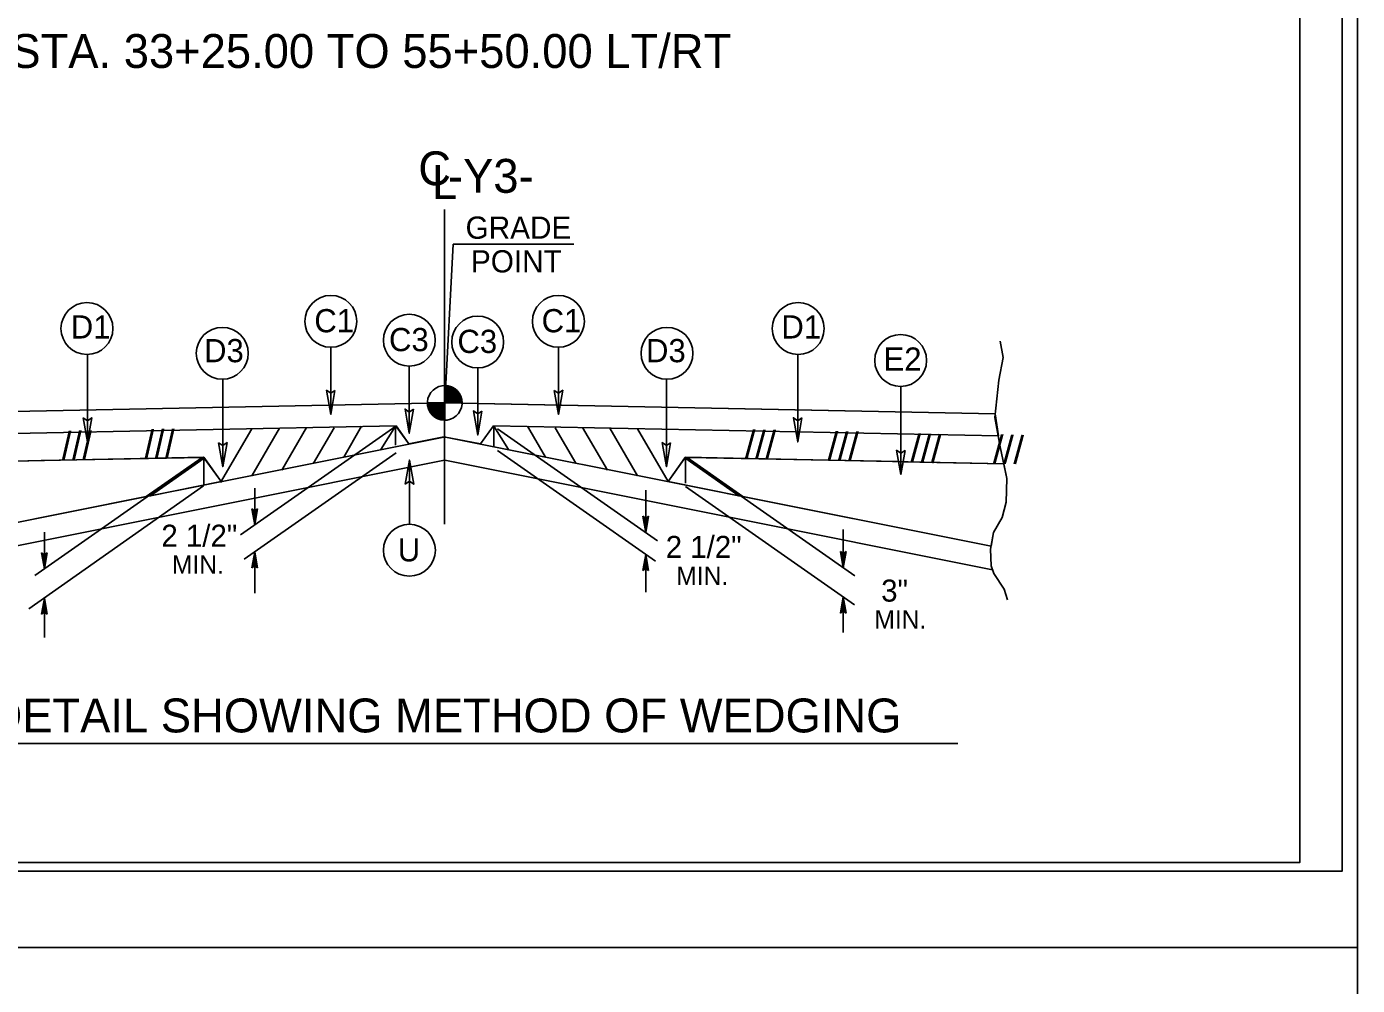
# Model space of a CAD drawing. Extents: x 1901718 to 1902220, y 193828 to 194187.
# Drawn here: x 1902095 to 1902134.24, y 194046.89 to 194075.18 of the extents above; entities that cross this region are included whole.
import ezdxf

# ---------------------------------------------------------------- set-up
doc = ezdxf.new("R2010")
doc.units = 0
for name, color, linetype in [('Old_Level_1', 7, 'Continuous'), ('Old_Level_11', 7, 'Continuous'), ('Old_Level_2', 7, 'Continuous'), ('Old_Level_20', 7, 'Continuous'), ('Old_Level_21', 7, 'Continuous'), ('Old_Level_3', 7, 'Continuous'), ('Prop Lane Arrow CELL', 7, 'Continuous'), ('Sheet Border Standard 30in CELL', 7, 'Continuous'), ('Sheet Cutting Line CELL', 7, 'Continuous'), ('Sheet Plot Border Inside CELL', 7, 'Continuous'), ('Sheet Plot Border Outside CELL', 7, 'Continuous')]:
    doc.layers.add(name, color=color, linetype=linetype)

msp = doc.modelspace()

# ---------------------------------------------------------------- linework, layer by layer
at = {"layer": 'Old_Level_1'}
for p, q in [((1902107.33, 194064.077), (1902107.33, 194064.588)), ((1902106.819, 194064.077), (1902107.33, 194064.077)), ((1902107.327, 194063.566), (1902107.327, 194064.071)), ((1902107.33, 194064.077), (1902107.33, 194063.566)), ((1902107.842, 194064.077), (1902107.33, 194064.077)), ((1902107.33, 194063.566), (1902107.33, 194064.077)), ((1902101.644, 194063.313), (1902100.721, 194061.732)), ((1902105.884, 194063.386), (1902101.309, 194060.183)), ((1902102.454, 194063.33), (1902101.638, 194061.928)), ((1902103.256, 194063.346), (1902102.523, 194062.089)), ((1902104.065, 194063.344), (1902103.457, 194062.303)), ((1902104.879, 194063.386), (1902104.35, 194062.478)), ((1902108.887, 194063.312), (1902113.6, 194060.011)), ((1902109.774, 194063.386), (1902110.304, 194062.478)), ((1902110.589, 194063.344), (1902111.197, 194062.303)), ((1902111.397, 194063.346), (1902112.131, 194062.089)), ((1902112.199, 194063.33), (1902113.016, 194061.928)), ((1902113.01, 194063.313), (1902113.919, 194061.755)), ((1902108.881, 194062.67), (1902113.548, 194059.403)), ((1902100.224, 194062.471), (1902090.84, 194062.283)), ((1902107.321, 194062.385), (1902091.207, 194059.162)), ((1902100.224, 194062.471), (1902095.242, 194058.982)), ((1902100.734, 194061.754), (1902100.224, 194062.471)), ((1902100.224, 194062.471), (1902100.224, 194061.652)), ((1902105.895, 194062.604), (1902101.418, 194059.469)), ((1902107.333, 194062.385), (1902123.484, 194059.154)), ((1902113.92, 194061.755), (1902114.429, 194062.471)), ((1902114.429, 194062.471), (1902123.814, 194062.283)), ((1902114.429, 194062.471), (1902114.429, 194061.71)), ((1902114.43, 194062.471), (1902119.42, 194058.976)), ((1902100.22, 194061.627), (1902095.069, 194058.001)), ((1902100.224, 194061.653), (1902098.59, 194061.326)), ((1902101.726, 194061.563), (1902101.726, 194060.475)), ((1902113.256, 194061.501), (1902113.256, 194060.253)), ((1902113.919, 194061.755), (1902116.064, 194061.326)), ((1902114.429, 194061.611), (1902119.411, 194058.121)), ((1902098.59, 194061.326), (1902091.213, 194059.851)), ((1902101.726, 194060.475), (1902101.642, 194060.952)), ((1902101.726, 194060.89), (1902101.642, 194060.952)), ((1902101.726, 194060.475), (1902101.654, 194060.943)), ((1902101.666, 194060.934), (1902101.726, 194060.475)), ((1902101.726, 194060.475), (1902101.678, 194060.926)), ((1902101.69, 194060.917), (1902101.726, 194060.475)), ((1902101.726, 194060.475), (1902101.702, 194060.908)), ((1902101.714, 194060.899), (1902101.726, 194060.475)), ((1902101.726, 194060.475), (1902101.811, 194060.952)), ((1902101.811, 194060.952), (1902101.726, 194060.89)), ((1902101.799, 194060.943), (1902101.726, 194060.475)), ((1902101.726, 194060.475), (1902101.786, 194060.934)), ((1902101.774, 194060.926), (1902101.726, 194060.475)), ((1902101.726, 194060.475), (1902101.762, 194060.917)), ((1902101.75, 194060.908), (1902101.726, 194060.475)), ((1902101.726, 194060.475), (1902101.738, 194060.899)), ((1902101.726, 194060.89), (1902101.726, 194060.475)), ((1902113.256, 194060.253), (1902113.172, 194060.731)), ((1902113.256, 194060.668), (1902113.172, 194060.731)), ((1902113.256, 194060.253), (1902113.183, 194060.722)), ((1902113.195, 194060.713), (1902113.256, 194060.253)), ((1902113.256, 194060.253), (1902113.208, 194060.704)), ((1902113.22, 194060.695), (1902113.256, 194060.253)), ((1902113.256, 194060.253), (1902113.231, 194060.686)), ((1902113.243, 194060.678), (1902113.256, 194060.253)), ((1902113.256, 194060.253), (1902113.34, 194060.731)), ((1902113.34, 194060.731), (1902113.256, 194060.668)), ((1902113.328, 194060.722), (1902113.256, 194060.253)), ((1902113.256, 194060.253), (1902113.316, 194060.713)), ((1902113.304, 194060.704), (1902113.256, 194060.253)), ((1902113.256, 194060.253), (1902113.292, 194060.695)), ((1902113.28, 194060.686), (1902113.256, 194060.253)), ((1902113.256, 194060.253), (1902113.268, 194060.678)), ((1902113.256, 194060.668), (1902113.256, 194060.253)), ((1902119.082, 194060.342), (1902119.082, 194059.213)), ((1902095.522, 194060.262), (1902095.522, 194059.177)), ((1902095.522, 194059.177), (1902095.437, 194059.655)), ((1902095.522, 194059.593), (1902095.437, 194059.655)), ((1902095.522, 194059.177), (1902095.449, 194059.647)), ((1902095.462, 194059.637), (1902095.522, 194059.177)), ((1902095.522, 194059.177), (1902095.475, 194059.629)), ((1902095.486, 194059.62), (1902095.522, 194059.177)), ((1902095.522, 194059.177), (1902095.498, 194059.611)), ((1902095.51, 194059.602), (1902095.522, 194059.177)), ((1902095.522, 194059.177), (1902095.606, 194059.655)), ((1902095.606, 194059.655), (1902095.522, 194059.593)), ((1902095.594, 194059.647), (1902095.522, 194059.177)), ((1902095.522, 194059.177), (1902095.582, 194059.637)), ((1902095.57, 194059.629), (1902095.522, 194059.177)), ((1902095.522, 194059.177), (1902095.558, 194059.62)), ((1902095.547, 194059.611), (1902095.522, 194059.177)), ((1902095.522, 194059.177), (1902095.534, 194059.602)), ((1902095.522, 194059.593), (1902095.522, 194059.177)), ((1902101.726, 194059.685), (1902101.642, 194059.207)), ((1902101.654, 194059.217), (1902101.726, 194059.685)), ((1902101.726, 194059.685), (1902101.666, 194059.225)), ((1902101.678, 194059.235), (1902101.726, 194059.685)), ((1902101.726, 194059.685), (1902101.69, 194059.243)), ((1902101.702, 194059.252), (1902101.726, 194059.685)), ((1902101.726, 194059.685), (1902101.714, 194059.261)), ((1902101.726, 194059.685), (1902101.726, 194058.459)), ((1902101.726, 194059.685), (1902101.811, 194059.207)), ((1902101.726, 194059.269), (1902101.726, 194059.685)), ((1902101.738, 194059.261), (1902101.726, 194059.685)), ((1902101.726, 194059.685), (1902101.75, 194059.252)), ((1902101.762, 194059.243), (1902101.726, 194059.685)), ((1902101.726, 194059.685), (1902101.774, 194059.235)), ((1902101.786, 194059.225), (1902101.726, 194059.685)), ((1902101.726, 194059.685), (1902101.799, 194059.217)), ((1902113.256, 194059.607), (1902113.172, 194059.13)), ((1902113.183, 194059.139), (1902113.256, 194059.607)), ((1902113.256, 194059.607), (1902113.195, 194059.148)), ((1902113.208, 194059.157), (1902113.256, 194059.607)), ((1902113.256, 194059.607), (1902113.22, 194059.166)), ((1902113.231, 194059.174), (1902113.256, 194059.607)), ((1902113.256, 194059.607), (1902113.243, 194059.183)), ((1902113.256, 194059.607), (1902113.256, 194058.491)), ((1902113.256, 194059.607), (1902113.34, 194059.13)), ((1902113.256, 194059.192), (1902113.256, 194059.607)), ((1902113.268, 194059.183), (1902113.256, 194059.607)), ((1902113.256, 194059.607), (1902113.28, 194059.174)), ((1902113.292, 194059.166), (1902113.256, 194059.607)), ((1902113.256, 194059.607), (1902113.304, 194059.157)), ((1902113.316, 194059.148), (1902113.256, 194059.607)), ((1902113.256, 194059.607), (1902113.328, 194059.139)), ((1902119.082, 194059.213), (1902118.998, 194059.69)), ((1902119.082, 194059.629), (1902118.998, 194059.69)), ((1902119.082, 194059.213), (1902119.01, 194059.681)), ((1902119.022, 194059.673), (1902119.082, 194059.213)), ((1902119.082, 194059.213), (1902119.033, 194059.665)), ((1902119.045, 194059.655), (1902119.082, 194059.213)), ((1902119.082, 194059.213), (1902119.058, 194059.647)), ((1902119.069, 194059.637), (1902119.082, 194059.213)), ((1902119.082, 194059.213), (1902119.166, 194059.69)), ((1902119.166, 194059.69), (1902119.082, 194059.629)), ((1902119.154, 194059.681), (1902119.082, 194059.213)), ((1902119.082, 194059.213), (1902119.142, 194059.673)), ((1902119.13, 194059.665), (1902119.082, 194059.213)), ((1902119.082, 194059.213), (1902119.117, 194059.655)), ((1902119.106, 194059.647), (1902119.082, 194059.213)), ((1902119.082, 194059.213), (1902119.094, 194059.637)), ((1902119.082, 194059.629), (1902119.082, 194059.213)), ((1902101.642, 194059.207), (1902101.726, 194059.269)), ((1902101.726, 194059.269), (1902101.811, 194059.207)), ((1902113.172, 194059.13), (1902113.256, 194059.192)), ((1902113.256, 194059.192), (1902113.34, 194059.13)), ((1902095.522, 194058.319), (1902095.437, 194057.842)), ((1902095.45, 194057.851), (1902095.522, 194058.319)), ((1902095.522, 194058.319), (1902095.462, 194057.86)), ((1902095.475, 194057.868), (1902095.522, 194058.319)), ((1902095.522, 194058.319), (1902095.486, 194057.877)), ((1902095.498, 194057.886), (1902095.522, 194058.319)), ((1902095.522, 194058.319), (1902095.51, 194057.894)), ((1902095.522, 194058.319), (1902095.522, 194057.159)), ((1902095.522, 194058.319), (1902095.606, 194057.842)), ((1902095.522, 194057.904), (1902095.522, 194058.319)), ((1902095.534, 194057.894), (1902095.522, 194058.319)), ((1902095.522, 194058.319), (1902095.547, 194057.886)), ((1902095.559, 194057.877), (1902095.522, 194058.319)), ((1902095.522, 194058.319), (1902095.57, 194057.868)), ((1902095.582, 194057.86), (1902095.522, 194058.319)), ((1902095.522, 194058.319), (1902095.594, 194057.851)), ((1902119.082, 194058.352), (1902118.998, 194057.875)), ((1902119.01, 194057.884), (1902119.082, 194058.352)), ((1902119.082, 194058.352), (1902119.022, 194057.893)), ((1902119.033, 194057.902), (1902119.082, 194058.352)), ((1902119.082, 194058.352), (1902119.045, 194057.911)), ((1902119.058, 194057.92), (1902119.082, 194058.352)), ((1902119.082, 194058.352), (1902119.069, 194057.928)), ((1902119.082, 194058.352), (1902119.082, 194057.305)), ((1902119.082, 194058.352), (1902119.166, 194057.875)), ((1902119.082, 194057.938), (1902119.082, 194058.352)), ((1902119.094, 194057.928), (1902119.082, 194058.352)), ((1902119.082, 194058.352), (1902119.106, 194057.92)), ((1902119.117, 194057.911), (1902119.082, 194058.352)), ((1902119.082, 194058.352), (1902119.13, 194057.902)), ((1902119.142, 194057.893), (1902119.082, 194058.352)), ((1902119.082, 194058.352), (1902119.154, 194057.884)), ((1902118.998, 194057.875), (1902119.082, 194057.938)), ((1902119.082, 194057.938), (1902119.166, 194057.875)), ((1902095.437, 194057.842), (1902095.522, 194057.904)), ((1902095.522, 194057.904), (1902095.606, 194057.842))]:
    msp.add_line(p, q, dxfattribs=at)
for points in [[(1902123.714, 194065.896), (1902123.8, 194065.42), (1902123.671, 194064.744), (1902123.555, 194063.649), (1902123.714, 194062.785), (1902123.901, 194061.849), (1902123.887, 194061.143), (1902123.771, 194060.697), (1902123.512, 194060.25), (1902123.426, 194059.761), (1902123.44, 194059.271), (1902123.526, 194059.04), (1902123.828, 194058.579), (1902123.929, 194058.262)], [(1902107.335, 194064.588), (1902107.335, 194064.588), (1902107.335, 194064.077)], [(1902107.345, 194064.588), (1902107.345, 194064.077)], [(1902107.356, 194064.588), (1902107.356, 194064.077)], [(1902107.366, 194064.587), (1902107.366, 194064.077)], [(1902107.377, 194064.587), (1902107.377, 194064.077)], [(1902107.386, 194064.585), (1902107.386, 194064.077)], [(1902107.397, 194064.585), (1902107.397, 194064.077)], [(1902107.406, 194064.583), (1902107.406, 194064.077)], [(1902107.417, 194064.581), (1902107.417, 194064.077)], [(1902107.427, 194064.579), (1902107.427, 194064.077)], [(1902107.438, 194064.578), (1902107.438, 194064.077)], [(1902107.448, 194064.575), (1902107.448, 194064.077)], [(1902107.458, 194064.572), (1902107.458, 194064.077)], [(1902107.468, 194064.569), (1902107.468, 194064.077)], [(1902107.478, 194064.566), (1902107.478, 194064.077)], [(1902107.488, 194064.563), (1902107.488, 194064.077)], [(1902107.499, 194064.56), (1902107.499, 194064.077)], [(1902107.509, 194064.556), (1902107.509, 194064.077)], [(1902107.52, 194064.552), (1902107.52, 194064.077)], [(1902107.53, 194064.548), (1902107.529, 194064.077)], [(1902107.54, 194064.543), (1902107.54, 194064.077)], [(1902107.55, 194064.539), (1902107.55, 194064.077)], [(1902107.56, 194064.534), (1902107.56, 194064.077)], [(1902107.571, 194064.528), (1902107.571, 194064.077)], [(1902107.581, 194064.522), (1902107.581, 194064.077)], [(1902107.591, 194064.516), (1902107.591, 194064.077)], [(1902107.602, 194064.51), (1902107.601, 194064.077)], [(1902107.612, 194064.505), (1902107.612, 194064.077)], [(1902107.621, 194064.497), (1902107.621, 194064.077)], [(1902107.631, 194064.49), (1902107.631, 194064.077)], [(1902107.642, 194064.482), (1902107.642, 194064.077)], [(1902107.652, 194064.474), (1902107.652, 194064.077)], [(1902107.663, 194064.466), (1902107.663, 194064.077)], [(1902107.673, 194064.457), (1902107.673, 194064.077)], [(1902107.684, 194064.447), (1902107.684, 194064.077)], [(1902107.693, 194064.438), (1902107.693, 194064.077)], [(1902107.703, 194064.427), (1902107.703, 194064.077)], [(1902107.714, 194064.415), (1902107.714, 194064.077)], [(1902107.724, 194064.403), (1902107.724, 194064.077)], [(1902107.735, 194064.39), (1902107.735, 194064.077)], [(1902107.745, 194064.377), (1902107.744, 194064.077)], [(1902107.755, 194064.363), (1902107.755, 194064.077)], [(1902107.764, 194064.346), (1902107.764, 194064.077)], [(1902107.775, 194064.329), (1902107.775, 194064.077)], [(1902107.785, 194064.311), (1902107.785, 194064.077)], [(1902107.796, 194064.289), (1902107.796, 194064.077)], [(1902107.806, 194064.265), (1902107.806, 194064.077)], [(1902107.816, 194064.236), (1902107.816, 194064.077)], [(1902107.827, 194064.202), (1902107.827, 194064.077)], [(1902106.821, 194064.077), (1902106.821, 194064.021)], [(1902106.832, 194064.077), (1902106.832, 194063.961)], [(1902106.843, 194064.077), (1902106.843, 194063.924)], [(1902106.853, 194064.077), (1902106.853, 194063.895)], [(1902106.862, 194064.077), (1902106.862, 194063.869)], [(1902106.872, 194064.077), (1902106.872, 194063.848)], [(1902106.882, 194064.077), (1902106.882, 194063.829)], [(1902106.893, 194064.077), (1902106.893, 194063.811)], [(1902106.903, 194064.077), (1902106.903, 194063.795)], [(1902106.914, 194064.077), (1902106.914, 194063.779)], [(1902106.924, 194064.077), (1902106.924, 194063.766)], [(1902106.934, 194064.077), (1902106.934, 194063.753)], [(1902106.944, 194064.077), (1902106.944, 194063.741)], [(1902106.954, 194064.077), (1902106.954, 194063.729)], [(1902106.965, 194064.077), (1902106.965, 194063.719)], [(1902106.975, 194064.077), (1902106.975, 194063.71)], [(1902106.986, 194064.077), (1902106.986, 194063.699)], [(1902106.996, 194064.077), (1902106.995, 194063.69)], [(1902107.005, 194064.077), (1902107.005, 194063.681)], [(1902107.016, 194064.077), (1902107.016, 194063.674)], [(1902107.026, 194064.077), (1902107.026, 194063.666)], [(1902107.037, 194064.077), (1902107.037, 194063.659)], [(1902107.047, 194064.077), (1902107.047, 194063.651)], [(1902107.057, 194064.077), (1902107.057, 194063.644)], [(1902107.067, 194064.077), (1902107.067, 194063.638)], [(1902107.077, 194064.077), (1902107.077, 194063.632)], [(1902107.087, 194064.077), (1902107.087, 194063.627)], [(1902107.097, 194064.077), (1902107.097, 194063.621)], [(1902107.108, 194064.077), (1902107.108, 194063.616)], [(1902107.118, 194064.077), (1902107.118, 194063.611)], [(1902107.129, 194064.077), (1902107.129, 194063.606)], [(1902107.139, 194064.077), (1902107.139, 194063.603)], [(1902107.149, 194064.077), (1902107.149, 194063.599)], [(1902107.16, 194064.077), (1902107.16, 194063.594)], [(1902107.169, 194064.077), (1902107.169, 194063.591)], [(1902107.18, 194064.077), (1902107.18, 194063.588)], [(1902107.19, 194064.077), (1902107.19, 194063.585)], [(1902107.2, 194064.077), (1902107.2, 194063.583)], [(1902107.211, 194064.077), (1902107.21, 194063.579)], [(1902107.22, 194064.077), (1902107.22, 194063.578)], [(1902107.231, 194064.077), (1902107.231, 194063.575)], [(1902107.24, 194064.077), (1902107.24, 194063.573)], [(1902107.251, 194064.077), (1902107.251, 194063.572)], [(1902107.261, 194064.077), (1902107.261, 194063.57)], [(1902107.272, 194064.077), (1902107.272, 194063.569)], [(1902107.282, 194064.077), (1902107.282, 194063.567)], [(1902107.292, 194064.077), (1902107.292, 194063.567)], [(1902107.303, 194064.077), (1902107.302, 194063.566)], [(1902107.312, 194064.077), (1902107.312, 194063.566)], [(1902107.323, 194064.077), (1902107.323, 194063.566), (1902107.323, 194063.566)], [(1902107.836, 194064.149), (1902107.836, 194064.077)]]:
    msp.add_lwpolyline(points, dxfattribs=at)
for start, end in [(358.0003, 356.1713), (359.9905, 89.9905), (179.9905, 268.7186), (269.6533, 269.9905)]:
    msp.add_arc((1902107.33, 194064.077), 0.512, start, end, dxfattribs=at)
at = {"layer": 'Old_Level_11'}
for p, q in [((1902107.326, 194060.497), (1902107.326, 194069.78)), ((1902096.792, 194065.504), (1902096.792, 194062.923)), ((1902103.971, 194065.717), (1902103.971, 194063.739)), ((1902110.682, 194065.717), (1902110.682, 194063.739)), ((1902117.74, 194065.504), (1902117.74, 194062.923)), ((1902106.284, 194065.16), (1902106.284, 194063.182)), ((1902108.301, 194065.107), (1902108.301, 194063.129)), ((1902100.783, 194064.775), (1902100.783, 194062.194)), ((1902113.869, 194064.775), (1902113.869, 194062.194)), ((1902120.781, 194064.563), (1902120.781, 194061.968)), ((1902107.326, 194064.077), (1902091.091, 194063.753)), ((1902107.326, 194064.077), (1902123.563, 194063.753)), ((1902107.328, 194064.077), (1902123.563, 194063.753)), ((1902123.563, 194063.753), (1902123.656, 194063.101)), ((1902105.902, 194063.399), (1902090.998, 194063.101)), ((1902107.351, 194063.079), (1902091.213, 194059.851)), ((1902105.441, 194062.704), (1902105.881, 194063.393)), ((1902105.881, 194063.393), (1902105.881, 194062.827)), ((1902106.267, 194062.864), (1902105.902, 194063.399)), ((1902105.902, 194063.381), (1902106.267, 194062.864)), ((1902107.303, 194063.079), (1902106.267, 194062.864)), ((1902107.303, 194063.079), (1902123.442, 194059.851)), ((1902108.387, 194062.864), (1902107.303, 194063.079)), ((1902108.763, 194063.399), (1902108.387, 194062.864)), ((1902108.763, 194063.399), (1902123.656, 194063.101)), ((1902109.213, 194062.704), (1902108.773, 194063.393)), ((1902108.773, 194063.393), (1902108.773, 194062.769)), ((1902100.179, 194062.47), (1902095.427, 194062.375)), ((1902098.525, 194061.312), (1902100.179, 194062.47)), ((1902106.288, 194060.494), (1902106.288, 194062.388)), ((1902114.531, 194062.47), (1902114.475, 194062.47)), ((1902114.475, 194062.47), (1902116.125, 194061.315)), ((1902120.714, 194062.345), (1902114.531, 194062.47)), ((1902123.814, 194062.283), (1902120.845, 194062.342)), ((1902091.212, 194059.851), (1902098.525, 194061.312)), ((1902116.125, 194061.315), (1902116.125, 194061.315)), ((1902116.125, 194061.315), (1902116.125, 194061.315)), ((1902116.125, 194061.315), (1902116.125, 194061.315)), ((1902116.125, 194061.315), (1902116.125, 194061.315)), ((1902116.125, 194061.315), (1902116.125, 194061.315)), ((1902116.125, 194061.315), (1902116.125, 194061.315)), ((1902116.125, 194061.315), (1902123.442, 194059.851)), ((1902123.442, 194059.851), (1902123.512, 194060.25)), ((1902123.442, 194059.851), (1902123.442, 194059.851)), ((1902093.164, 194054.031), (1902122.459, 194054.031))]:
    msp.add_line(p, q, dxfattribs=at)
for points in [[(1902104.093, 194064.447), (1902103.971, 194063.739), (1902103.845, 194064.451), (1902103.971, 194064.361)], [(1902110.56, 194064.447), (1902110.682, 194063.739), (1902110.808, 194064.451), (1902110.682, 194064.361)], [(1902106.406, 194063.891), (1902106.284, 194063.182), (1902106.158, 194063.895), (1902106.284, 194063.804)], [(1902108.424, 194063.837), (1902108.301, 194063.129), (1902108.175, 194063.841), (1902108.301, 194063.751)], [(1902096.67, 194063.632), (1902096.792, 194062.923), (1902096.918, 194063.636), (1902096.792, 194063.545)], [(1902117.862, 194063.632), (1902117.74, 194062.923), (1902117.614, 194063.636), (1902117.74, 194063.545)], [(1902100.661, 194062.902), (1902100.783, 194062.194), (1902100.909, 194062.906), (1902100.783, 194062.816)], [(1902113.992, 194062.902), (1902113.869, 194062.194), (1902113.743, 194062.906), (1902113.869, 194062.816)], [(1902120.903, 194062.676), (1902120.781, 194061.968), (1902120.655, 194062.68), (1902120.781, 194062.59)], [(1902100.734, 194061.754), (1902100.239, 194062.45), (1902098.652, 194061.339)], [(1902106.166, 194061.679), (1902106.288, 194062.388), (1902106.414, 194061.675), (1902106.288, 194061.766)], [(1902114.415, 194062.451), (1902113.92, 194061.755), (1902116.002, 194061.339)]]:
    msp.add_lwpolyline(points, close=True, dxfattribs=at)
for points in [[(1902095.427, 194062.375), (1902094.237, 194062.351), (1902094.171, 194061.968), (1902094.104, 194062.348)], [(1902120.845, 194062.342), (1902120.781, 194061.968), (1902120.714, 194062.345)], [(1902123.512, 194060.25), (1902123.771, 194060.697), (1902123.887, 194061.143), (1902123.901, 194061.849), (1902123.814, 194062.283)]]:
    msp.add_lwpolyline(points, dxfattribs=at)
for centre in [(1902096.778, 194066.27), (1902103.971, 194066.482), (1902110.682, 194066.482), (1902117.754, 194066.27), (1902106.284, 194065.925), (1902108.302, 194065.872), (1902100.769, 194065.54), (1902113.884, 194065.54), (1902120.774, 194065.329), (1902106.288, 194059.729)]:
    msp.add_circle(centre, 0.765, dxfattribs=at)
at = {"layer": 'Old_Level_3'}
for q in [(1902107.328, 194064.077), (1902111.135, 194068.761)]:
    msp.add_line((1902107.578, 194068.761), q, dxfattribs=at)
at = {"layer": 'Sheet Border Standard 30in CELL'}
msp.add_lwpolyline([(1902132.544, 194155.514), (1901982.544, 194155.514), (1901982.544, 194050.514), (1902132.544, 194050.514)], close=True, dxfattribs=at)
at = {"layer": 'Sheet Cutting Line CELL'}
for p, q in [((1901965.844, 194048.014), (1902134.244, 194048.014)), ((1902134.244, 194048.014), (1901965.844, 194048.014))]:
    msp.add_line(p, q, dxfattribs=at)
at = {"layer": 'Sheet Plot Border Inside CELL'}
msp.add_lwpolyline([(1902133.794, 194155.769), (1901967.144, 194155.769), (1901967.144, 194050.259), (1902133.794, 194050.259)], close=True, dxfattribs=at)
at = {"layer": 'Sheet Plot Border Outside CELL'}
for points in [[(1902134.244, 194158.014), (1901965.844, 194158.014), (1901965.844, 194048.014), (1902134.244, 194048.014)], [(1902134.244, 194048.014), (1901965.844, 194048.014), (1901965.844, 193938.014), (1902134.244, 193938.014)]]:
    msp.add_lwpolyline(points, close=True, dxfattribs=at)

# ---------------------------------------------------------------- texts
at = {"layer": 'Old_Level_1'}
for height, rotation, p in [(0.8139, 1.1445, (1902096.036, 194062.395)), (0.8139, 1.1463, (1902098.477, 194062.445)), (0.8139, 358.8553, (1902116.178, 194062.445)), (0.8142, 358.8554, (1902121.057, 194062.323)), (0.8142, 358.8537, (1902123.491, 194062.294))]:
    msp.add_text('/// ', height=height, rotation=rotation, dxfattribs=at).set_placement(p)
at = {"layer": 'Old_Level_11'}
for s, p in [('GRADE', (1902107.944, 194068.919)), ('POINT', (1902108.102, 194067.925))]:
    msp.add_text(s, height=0.656, dxfattribs=at).set_placement(p)
msp.add_text('/// ', height=0.8139, rotation=358.8536, dxfattribs=at).set_placement((1902118.619, 194062.395))
at = {"layer": 'Old_Level_2'}
msp.add_text('C', height=1, dxfattribs=at).set_placement((1902106.55, 194070.496))
for s, p in [('-Y3-', (1902107.425, 194070.276)), ('L', (1902106.952, 194070.092))]:
    msp.add_text(s, height=1, rotation=359.9469, dxfattribs=at).set_placement(p)
at = {"layer": 'Old_Level_20'}
for s, height, p in [('D1', 0.6851, (1902096.302, 194065.976)), ('C1', 0.6851, (1902103.484, 194066.159)), ('C1', 0.6851, (1902110.187, 194066.159)), ('D1', 0.6851, (1902117.257, 194065.976)), ('C3', 0.6851, (1902105.686, 194065.602)), ('C3', 0.6851, (1902107.704, 194065.549)), ('D3', 0.6851, (1902100.232, 194065.276)), ('D3', 0.6851, (1902113.265, 194065.276)), ('E2', 0.6851, (1902120.27, 194065.027)), ('2 1/2"', 0.6491, (1902098.973, 194059.834)), ('U', 0.685, (1902105.945, 194059.4)), ('2 1/2"', 0.6491, (1902113.846, 194059.504)), ('3"', 0.6491, (1902120.2, 194058.214))]:
    msp.add_text(s, height=height, dxfattribs=at).set_placement(p)
at = {"layer": 'Old_Level_21'}
for s, height, p in [('MIN.', 0.5424, (1902099.285, 194059.037)), ('MIN.', 0.5424, (1902114.158, 194058.705)), ('MIN.', 0.5424, (1902120.001, 194057.416)), ('DETAIL SHOWING METHOD OF WEDGING', 1, (1902093.904, 194054.355))]:
    msp.add_text(s, height=height, dxfattribs=at).set_placement(p)
at = {"layer": 'Prop Lane Arrow CELL'}
msp.add_text('-L- STA. 33+25.00 TO 55+50.00 LT/RT', height=0.99999, dxfattribs=at).set_placement((1902092.514, 194073.958))

doc.saveas('drawing.dxf')
